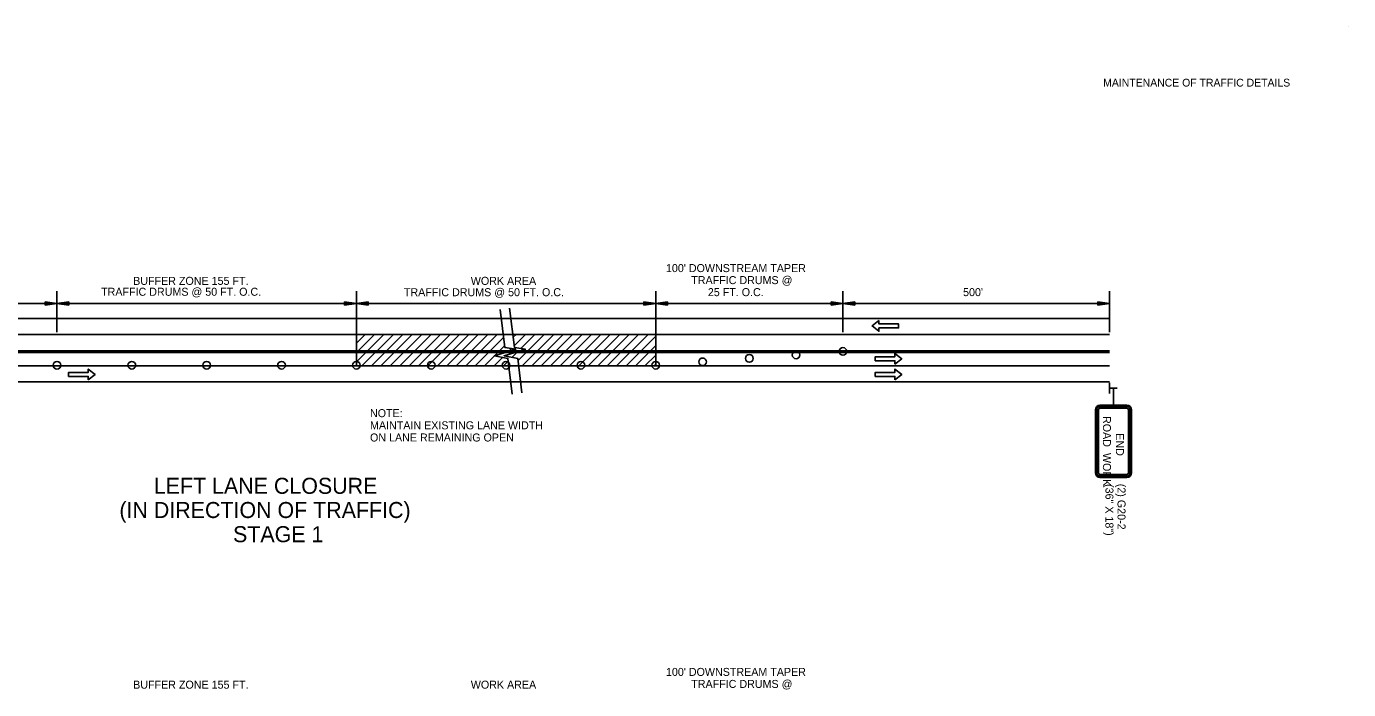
# Model space of a CAD drawing. Extents: x 1930579 to 1937984, y 596452 to 597630.
# Drawn here: x 1936993 to 1937984, y 597133 to 597630 of the extents above; entities that cross this region are included whole.
import ezdxf

# ---------------------------------------------------------------- set-up
doc = ezdxf.new("R2010")
doc.units = 0
for name, color, linetype in [('Default', 7, 'Continuous'), ('P_TC_Signs_Temporary', 7, 'Continuous'), ('R_Annotation', 7, 'Continuous'), ('R_Border', 7, 'Continuous'), ('R_Striping', 7, 'Continuous')]:
    doc.layers.add(name, color=color, linetype=linetype)

msp = doc.modelspace()

# ---------------------------------------------------------------- linework, layer by layer
at = {"layer": 'Default'}
for p, q in [((1937015.53, 597422.4), (1937006.66, 597423.73)), ((1937006.66, 597423.73), (1937006.66, 597421.07)), ((1937015.53, 597431.71), (1937015.53, 597400.99)), ((1937015.53, 597422.4), (1937024.4, 597423.73)), ((1937024.4, 597423.73), (1937024.4, 597421.07)), ((1937231.17, 597421.07), (1937231.17, 597423.73)), ((1937231.17, 597423.73), (1937240.04, 597422.4)), ((1937240.04, 597431.71), (1937240.04, 597375.6)), ((1937248.9, 597423.73), (1937240.04, 597422.4)), ((1937248.9, 597421.07), (1937248.9, 597423.73)), ((1937455.68, 597421.07), (1937455.68, 597423.73)), ((1937455.68, 597423.73), (1937464.54, 597422.4)), ((1937464.54, 597431.71), (1937464.54, 597375.6)), ((1937473.41, 597423.73), (1937464.54, 597422.4)), ((1937473.41, 597421.07), (1937473.41, 597423.73)), ((1937595.99, 597421.07), (1937595.99, 597423.73)), ((1937595.99, 597423.73), (1937604.86, 597422.4)), ((1937604.86, 597431.71), (1937604.86, 597400.99)), ((1937613.73, 597423.73), (1937604.86, 597422.4)), ((1937613.73, 597421.07), (1937613.73, 597423.73)), ((1937795.99, 597421.07), (1937795.99, 597423.73)), ((1937795.99, 597423.73), (1937804.86, 597422.4)), ((1937804.86, 597431.71), (1937804.86, 597400.99)), ((1937015.53, 597422.4), (1936791.02, 597422.4)), ((1937006.66, 597421.07), (1937015.53, 597422.4)), ((1937240.04, 597422.4), (1937015.53, 597422.4)), ((1937024.4, 597421.07), (1937015.53, 597422.4)), ((1937240.04, 597422.4), (1937231.17, 597421.07)), ((1937464.54, 597422.4), (1937240.04, 597422.4)), ((1937240.04, 597422.4), (1937248.9, 597421.07)), ((1937464.54, 597422.4), (1937455.68, 597421.07)), ((1937604.86, 597422.4), (1937464.54, 597422.4)), ((1937464.54, 597422.4), (1937473.41, 597421.07)), ((1937604.86, 597422.4), (1937595.99, 597421.07)), ((1937804.86, 597422.4), (1937604.86, 597422.4)), ((1937604.86, 597422.4), (1937613.73, 597421.07)), ((1937804.86, 597422.4), (1937795.99, 597421.07)), ((1937804.86, 597411.17), (1936452.69, 597411.17)), ((1937804.86, 597399.17), (1936452.69, 597399.17)), ((1937240.04, 597392.61), (1937246.6, 597399.17)), ((1937240.05, 597385.55), (1937253.67, 597399.17)), ((1937240.22, 597378.65), (1937260.74, 597399.17)), ((1937244.24, 597375.6), (1937267.81, 597399.17)), ((1937251.31, 597375.6), (1937274.88, 597399.17)), ((1937258.39, 597375.6), (1937281.95, 597399.17)), ((1937265.46, 597375.6), (1937289.02, 597399.17)), ((1937272.53, 597375.6), (1937296.09, 597399.17)), ((1937279.6, 597375.6), (1937303.17, 597399.17)), ((1937286.67, 597375.6), (1937310.24, 597399.17)), ((1937293.74, 597375.6), (1937317.31, 597399.17)), ((1937300.81, 597375.6), (1937324.38, 597399.17)), ((1937307.88, 597375.6), (1937331.45, 597399.17)), ((1937314.95, 597375.6), (1937338.52, 597399.17)), ((1937322.03, 597375.6), (1937345.59, 597399.17)), ((1937329.1, 597375.6), (1937350.36, 597396.87)), ((1937357.62, 597397.06), (1937359.73, 597399.17)), ((1937357.62, 597397.06), (1937359.73, 597399.17)), ((1937358.41, 597390.77), (1937366.81, 597399.17)), ((1937361.21, 597379.43), (1937380.95, 597399.17)), ((1937363.4, 597388.69), (1937373.88, 597399.17)), ((1937364.45, 597375.6), (1937388.02, 597399.17)), ((1937371.52, 597375.6), (1937395.09, 597399.17)), ((1937378.59, 597375.6), (1937402.16, 597399.17)), ((1937385.67, 597375.6), (1937409.23, 597399.17)), ((1937392.74, 597375.6), (1937416.3, 597399.17)), ((1937399.81, 597375.6), (1937423.37, 597399.17)), ((1937406.88, 597375.6), (1937430.45, 597399.17)), ((1937413.95, 597375.6), (1937437.52, 597399.17)), ((1937421.02, 597375.6), (1937444.59, 597399.17)), ((1937428.09, 597375.6), (1937451.66, 597399.17)), ((1937435.16, 597375.6), (1937458.73, 597399.17)), ((1937442.23, 597375.6), (1937464.54, 597397.91)), ((1937804.86, 597386.94), (1936452.69, 597386.94)), ((1937804.86, 597385.79), (1936452.69, 597385.79)), ((1937336.17, 597375.6), (1937351.15, 597390.58)), ((1937350.85, 597383.22), (1937350.89, 597383.26)), ((1937354.06, 597386.43), (1937356.29, 597388.66)), ((1937356.79, 597382.08), (1937361.04, 597386.33)), ((1937449.3, 597375.6), (1937464.54, 597390.84)), ((1937456.38, 597375.6), (1937464.54, 597383.77)), ((1937804.86, 597375.6), (1936452.69, 597375.6)), ((1937343.24, 597375.6), (1937349.69, 597382.05)), ((1937350.31, 597375.6), (1937353.95, 597379.24)), ((1937463.45, 597375.6), (1937464.54, 597376.7)), ((1937463.45, 597375.6), (1937464.54, 597376.7)), ((1937804.86, 597363.6), (1936452.69, 597363.6)), ((1937804.86, 597354.95), (1937804.86, 597362.93)), ((1937804.98, 597358.92), (1937810.42, 597358.92))]:
    msp.add_line(p, q, dxfattribs=at)
for points in [[(1937347.74, 597417.86), (1937351.28, 597389.54), (1937359.53, 597388.09), (1937343.51, 597383.23), (1937353.71, 597381.28), (1937356.93, 597354.52)], [(1937354.91, 597418.76), (1937358.56, 597389.54), (1937366.82, 597388.09), (1937350.79, 597383.23), (1937360.99, 597381.28), (1937364.11, 597355.38)]]:
    msp.add_lwpolyline(points, dxfattribs=at)
for centre in [(1937534.7, 597381.27), (1937569.78, 597383.86), (1937604.86, 597386.45), (1937015.53, 597376.09), (1937071.66, 597376.09), (1937127.78, 597376.09), (1937183.91, 597376.09), (1937240.04, 597376.09), (1937296.16, 597376.09), (1937352.29, 597376.09), (1937408.42, 597376.09), (1937464.54, 597376.09), (1937499.62, 597378.68)]:
    msp.add_circle(centre, 2.87, dxfattribs=at)
at = {"layer": 'P_TC_Signs_Temporary'}
for p, q in [((1937817.83, 597346.12), (1937797.58, 597346.12)), ((1937817.83, 597345.18), (1937797.58, 597345.18)), ((1937817.83, 597343.87), (1937797.58, 597343.87)), ((1937794.2, 597342.74), (1937794.2, 597295.49)), ((1937795.14, 597342.74), (1937795.14, 597295.49)), ((1937796.45, 597342.74), (1937796.45, 597295.49)), ((1937818.95, 597295.49), (1937818.95, 597342.74)), ((1937820.26, 597295.49), (1937820.26, 597342.74)), ((1937821.2, 597295.49), (1937821.2, 597342.74)), ((1937797.58, 597294.37), (1937817.83, 597294.37)), ((1937797.58, 597293.05), (1937817.83, 597293.05)), ((1937797.58, 597292.12), (1937817.83, 597292.12))]:
    msp.add_line(p, q, dxfattribs=at)
for centre, radius, start, end in [((1937797.58, 597342.74), 3.38, 90, 180), ((1937797.58, 597342.74), 2.44, 90, 180), ((1937797.58, 597342.74), 1.13, 90, 180), ((1937817.83, 597342.74), 3.37, 360, 90), ((1937817.83, 597342.74), 2.44, 360, 90), ((1937817.83, 597342.74), 1.13, 360, 90), ((1937797.58, 597295.49), 3.37, 180, 270), ((1937797.58, 597295.49), 2.44, 180, 270), ((1937797.58, 597295.49), 1.13, 180, 270), ((1937817.83, 597295.49), 2.44, 270, 360), ((1937817.83, 597295.49), 1.13, 270, 360), ((1937817.83, 597295.49), 3.38, 270, 360)]:
    msp.add_arc(centre, radius, start, end, dxfattribs=at)
at = {"layer": 'R_Annotation'}
msp.add_line((1937807.7, 597358.91), (1937807.7, 597346.12), dxfattribs=at)
at = {"layer": 'R_Border'}
msp.add_line((1937984, 597629.92), (1937984, 597629.92), dxfattribs=at)
at = {"layer": 'R_Striping'}
for points in [[(1937631.9, 597409.53), (1937626.7, 597405.53), (1937631.9, 597401.53), (1937631.9, 597404.03), (1937646.61, 597404.03), (1937646.61, 597407.03), (1937631.9, 597407.03)], [(1937643.82, 597377.02), (1937649.01, 597381.02), (1937643.82, 597385.02), (1937643.82, 597382.52), (1937629.11, 597382.52), (1937629.11, 597379.52), (1937643.82, 597379.52)], [(1937038.98, 597365.27), (1937044.17, 597369.27), (1937038.98, 597373.27), (1937038.98, 597370.77), (1937024.27, 597370.77), (1937024.27, 597367.77), (1937038.98, 597367.77)], [(1937643.82, 597365.24), (1937649.01, 597369.24), (1937643.82, 597373.24), (1937643.82, 597370.74), (1937629.11, 597370.74), (1937629.11, 597367.74), (1937643.82, 597367.74)]]:
    msp.add_lwpolyline(points, close=True, dxfattribs=at)

# ---------------------------------------------------------------- texts
at = {"layer": 'Default'}
for s, height, p in [("100' DOWNSTREAM TAPER", 6, (1937472.18, 597445.9)), ('TRAFFIC DRUMS @', 6, (1937491.14, 597436.9)), ('TRAFFIC DRUMS @ 50 FT. O.C.', 6, (1937048.61, 597428.18)), ('BUFFER ZONE 155 FT.', 6, (1937072.66, 597436.34)), ('TRAFFIC DRUMS @ 50 FT. O.C.', 6, (1937275.67, 597427.85)), ('WORK AREA', 6, (1937325.83, 597436.34)), ('25 FT. O.C.', 6, (1937503.59, 597427.9)), ("500'", 6, (1937694.96, 597427.9)), ('LEFT LANE CLOSURE', 12, (1937088.13, 597279.8)), ('(IN DIRECTION OF TRAFFIC)', 12, (1937062.33, 597261.68)), ('STAGE 1', 12, (1937147.56, 597243.56)), ("100' DOWNSTREAM TAPER", 6, (1937472.18, 597143.38)), ('BUFFER ZONE 155 FT.', 6, (1937072.66, 597133.82)), ('WORK AREA', 6, (1937325.83, 597133.82)), ('TRAFFIC DRUMS @', 6, (1937491.14, 597134.38))]:
    msp.add_text(s, height=height, rotation=360, dxfattribs=at).set_placement(p)
at = {"layer": 'P_TC_Signs_Temporary'}
for s, p in [('ROAD  WORK', (1937799.83, 597338.08)), ('END', (1937809.58, 597325.15))]:
    msp.add_text(s, height=6, rotation=270, dxfattribs=at).set_placement(p)
at = {"layer": 'R_Annotation'}
for s, rotation, p in [('NOTE:', 360, (1937250.26, 597337.23)), ('MAINTAIN EXISTING LANE WIDTH', 360, (1937250.26, 597328.12)), ('ON LANE REMAINING OPEN', 360, (1937250.26, 597319.01)), ('(36" X 18")', 270, (1937801.7, 597287.12)), ('(2) G20-2', 270, (1937810.76, 597287.33))]:
    msp.add_text(s, height=6, rotation=rotation, dxfattribs=at).set_placement(p)
at = {"layer": 'R_Border'}
msp.add_text('MAINTENANCE OF TRAFFIC DETAILS', height=5.862, rotation=360, dxfattribs=at).set_placement((1937800, 597584.9))

doc.saveas('drawing.dxf')
